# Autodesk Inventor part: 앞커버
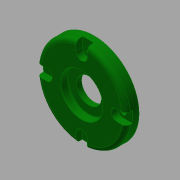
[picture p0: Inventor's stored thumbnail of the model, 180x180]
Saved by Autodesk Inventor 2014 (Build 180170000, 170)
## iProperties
Created: 2019-01
Part Number: 앞커버
Material: 알루미늄 6061
Document SubType Name: Modeling
Designer: mduedu
Density: 2.71 g/cm^3
Appearance: 진녹색
Mass: 65.0159 g
Surface Area: 90.7546 cm^2
Volume: 23.9911 cm^3
Author: mduedu
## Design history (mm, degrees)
sketch "스케치1"
  geometry: L1 (0, 0)-(9, 0); L2 (9, 0)-(9, 32); L3 (9, 32)-(0, 32); L4 (0, 32)-(0, 0); L5 (9, 0)-(12, 0); L6 (12, 0)-(12, 20); L7 (12, 20)-(9, 20); L8 (9, 20)-(9, 0)
  constraints: 16 end point, 4 parallel, 2 horizontal, 2 perpendicular
  dimensions: "d0" = 12 distance between parallel lines of L6 L4; "d2" = 64 diameter of L3 L1; "d3" = 40 diameter of L7 L5; "d4" = 3 distance between parallel lines of L6 L2
revolve "회전1" sketch "스케치1" stored, may be unused: angle "d5" = 90 deg
sketch "스케치2"
  geometry: L1 (0, -32)-(0, 32) reference; L2 (0, 32)-(9, 32) reference; L3 (9, 32)-(9, 20) reference; L4 (9, 20)-(12, 20) reference; L5 (12, 20)-(12, -20) reference; L6 (12, -20)-(9, -20) reference; L7 (9, -20)-(9, -32) reference; L8 (9, -32)-(0, -32) reference; L9 (0, 0)-(5.2, 0); L10 (5.2, 0)-(5.2, 15); L11 (5.2, 15)-(0, 15); L12 (0, 15)-(0, 0); L13 (5.2, 0)-(9, 0); L14 (9, 0)-(9, 9); L15 (9, 9)-(5.2, 9); L16 (5.2, 9)-(5.2, 0); L17 (9, 0)-(12, 0); L18 (12, 0)-(12, 15); L19 (12, 15)-(9, 15); L20 (9, 15)-(9, 0)
  constraints: 24 end point, 6 parallel, 3 horizontal, 3 perpendicular, 1 point on line
  dimensions: "d6" = 3 distance of L18.end L19.end; "d8" = 5.2 distance of L10.end L11.end; "d9" = 30 diameter of L11 L9; "d10" = 18 diameter of L15 L13; "d11" = 30 diameter of L19 L17
revolve "회전2" sketch "스케치2" stored, may be unused: angle "d12" = 90 deg
chamfer "모따기1" distance "d13" = 0.5; stored, may be unused: second distance "d14" = 2, angle "d15" = 30 deg
fillet "모깎기1" dims "d16" = 0.5
fillet "모깎기2" dims "d17" = 3
fillet "모깎기3" dims "d18" = 3
chamfer "모따기2" distance "d24" = 1; stored, may be unused: second distance "d25" = 2, angle "d26" = 45 deg
sketch "스케치3" dims "d19" = 50
  geometry: 6 further points
  constraints: 2 vertical alignment, 1 coincident, 7 other
  dimensions: "d22" = 360 deg dimension on point (0, 0) point (0, 25) (derived)
sketch "스케치4"
  geometry: 4 further points
  constraints: 4 other
hole "구멍1" sketch "스케치4" at (-25, 0), (0, -25), (25, 0), (0, 25) diameter "d27" = 4.5; stored, may be unused: countersink angle "d31" = 90 deg, drill point angle "d33" = 0 deg; dims "d28" = 6, "d29" = 8, "d30" = 4.6, "d32" = 8
sketch "스케치5"
  geometry: L1 (-4, 0)-(-4, 6.749); L2 (4, 0)-(4, 6.749); A1 r 4 centre (0, 0) between (0, 4) and (-4, 0) reference; A2 r 32 centre (0, -25) between (-4, 6.749) and (4, 6.749) reference; A3 r 4 centre (0, 0) between (-4, 0) and (4, 0); A4 r 32 centre (0, -25) between (4, 6.749) and (-4, 6.749); A5 r 4 centre (0, 0) between (4, 0) and (-4, 0); 1 further point
  constraints: 10 point on circle, 4 end point, 3 centre point, 2 coincident, 2 tangent, 1 parallel, 1 vertical
extrude "돌출1" cut sketch "스케치5" stored distance "d34" = 10; taper "d35" = 0 deg
node "솔리드1"
pattern_circular "원형 패턴1" dims angle "d37" = 360 deg
node "절단 모서리 투영1"
